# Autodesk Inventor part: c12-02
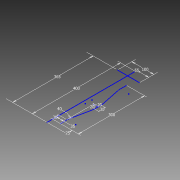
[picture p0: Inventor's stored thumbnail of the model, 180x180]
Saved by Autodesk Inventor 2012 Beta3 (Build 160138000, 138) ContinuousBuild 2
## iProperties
Created: 2011-01
Part Number: c12-02
Material: Default
Document SubType Name: Modeling
Designer: Beta-8540w
Density: 1 g/cm^3
Author: Beta-8540w
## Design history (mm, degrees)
sketch "Sketch1"
  geometry: L1 (0, 0)-(0, 400); L2 (-45, 365)-(55, 365); L3 (35, 25)-(35, 55); L4 (35.827, 63.092)-(54.173, 151.908); L5 (55, 160)-(55, 190); L6 (54.173, 198.092)-(35.827, 286.908); L7 (35, 295)-(35, 325); L8 (55, 175)-(35, 175); A1 r 40 centre (75, 55) between (35.827, 63.092) and (35, 55); A2 r 40 centre (15, 160) between (54.173, 151.908) and (55, 160); A3 r 40 centre (15, 190) between (55, 190) and (54.173, 198.092); A4 r 40 centre (75, 295) between (35, 295) and (35.827, 286.908)
  constraints: 16 end point, 8 point on circle, 8 tangent, 4 centre point, 3 equal radius, 3 perpendicular, 2 equal length, 1 collinear, 1 midpoint, 1 parallel, 1 vertical
  dimensions: "d0" = 400 distance of L1.start L1.end; "d2" = 365 distance from line of L2 L1.start; "d3" = 100 distance of L2.start L2.end; "d4" = 55 horizontal distance of L2.end L1.end; "d5" = 30 distance of L3.start L3.end; "d6" = 40 radius of A1; "d7" = 35 distance between parallel lines of L1 L3; "d8" = 25 vertical distance of L3.start L1.start; "d9" = 20 distance between parallel lines of L5 L3; "d10" = 30 distance of L5.start L5.end; "d11" = 300 distance of L7.end L3.start; "d12" = 20 distance of L8.start L8.end (= d9)
